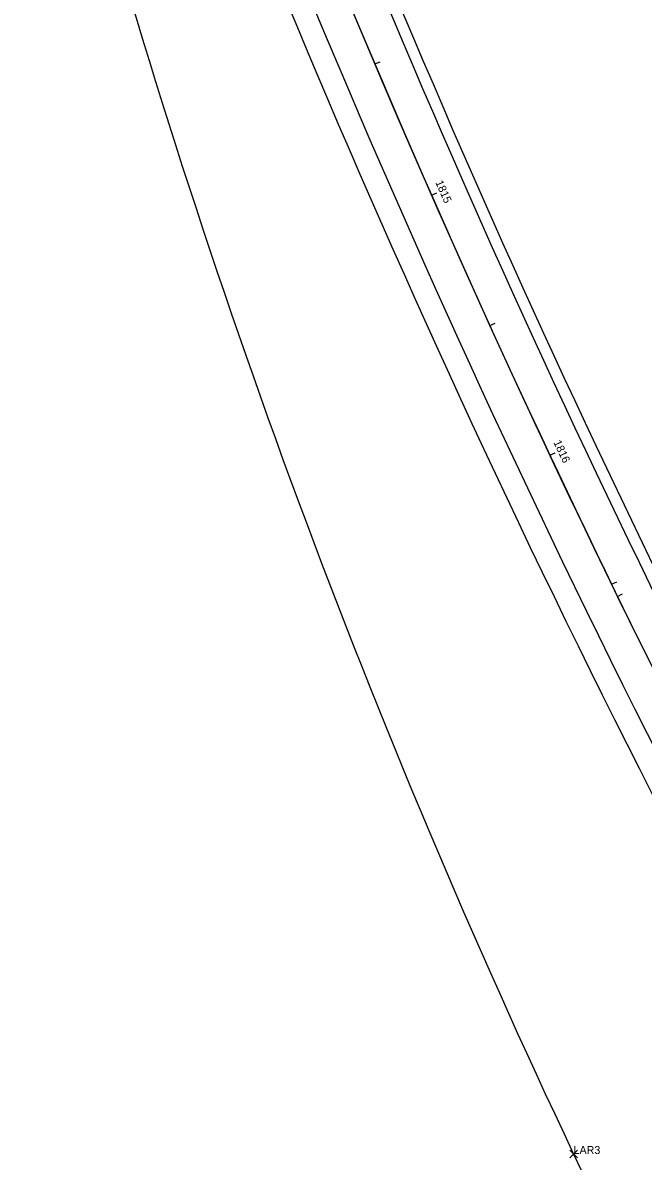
# Model space of a CAD drawing. Extents: x 6334 to 41599, y 9030 to 59113.
# Drawn here: x 20810.8 to 21027.9, y 34361.6 to 34759.9 of the extents above; entities that cross this region are included whole.
import ezdxf

# ---------------------------------------------------------------- set-up
doc = ezdxf.new("R2010")
doc.units = 0
for name, color, linetype in [('GE_X_CL_20', 7, 'Continuous'), ('GE_X_CL_50', 7, 'Continuous'), ('GK_Visualization', 7, 'Continuous'), ('PM_X_Lane_Line', 7, 'Continuous'), ('PV_X_EOP', 7, 'Continuous'), ('PV_X_Shoulder', 7, 'Continuous'), ('RW_X_Esmt_LA', 7, 'Continuous')]:
    doc.layers.add(name, color=color, linetype=linetype)

msp = doc.modelspace()

# ---------------------------------------------------------------- linework, layer by layer
at = {"layer": 'GE_X_CL_20'}
for p, q in [((20933.95, 34745.52), (20935.79, 34746.3)), ((20953.78, 34699.62), (20955.61, 34700.43)), ((20974.19, 34653.98), (20976.01, 34654.81)), ((20995.19, 34608.6), (20997, 34609.46)), ((21016.77, 34563.5), (21018.57, 34564.37)), ((21018.85, 34559.22), (21020.65, 34560.09))]:
    msp.add_line(p, q, dxfattribs=at)
msp.add_arc((24529.94, 36271.9), 3906.53, 186.21667, 209.21667, dxfattribs=at)
at = {"layer": 'GE_X_CL_50'}
msp.add_arc((32581.78, 39251.96), 12277.67, 194.525, 202.716667, dxfattribs=at)
at = {"layer": 'GK_Visualization'}
for p, q in [((21002.15, 34362.81), (21004.81, 34365.48)), ((21002.15, 34365.48), (21004.81, 34362.81))]:
    msp.add_line(p, q, dxfattribs=at)
for centre, radius, start, end in [((32581.78, 39251.96), 12277.67, 194.525, 202.716667), ((32581.78, 39251.96), 12277.67, 194.525, 202.716667), ((24529.91, 36271.94), 3906.53, 186.21497, 209.2138), ((24529.91, 36271.94), 3906.53, 186.21497, 209.2138), ((24529.94, 36271.9), 3906.53, 186.21667, 209.21667), ((24529.94, 36271.9), 3906.53, 186.21667, 209.21667)]:
    msp.add_arc(centre, radius, start, end, dxfattribs=at)
at = {"layer": 'PM_X_Lane_Line'}
for start in [186.21667, 191.33607]:
    msp.add_arc((24529.94, 36271.9), 3906.53, start, 209.21667, dxfattribs=at)
at = {"layer": 'PV_X_EOP'}
for centre, radius, start, end in [((24529.94, 36271.9), 3918.53, 191.33607, 209.21667), ((24531.79, 36272.61), 3896.49, 192.87045, 209.21252)]:
    msp.add_arc(centre, radius, start, end, dxfattribs=at)
at = {"layer": 'PV_X_Shoulder'}
for radius, start in [(3926.53, 191.34141), (3890.53, 192.86631)]:
    msp.add_arc((24529.94, 36271.9), radius, start, 209.21667, dxfattribs=at)
at = {"layer": 'RW_X_Esmt_LA'}
msp.add_line((21003.48, 34364.15), (21020.77, 34328.02), dxfattribs=at)
msp.add_arc((23569.82, 35580.33), 2839.93, 195.3477, 205.35619, dxfattribs=at)

# ---------------------------------------------------------------- texts
at = {"layer": 'GE_X_CL_20'}
for s, rotation, p in [('1815', 293.7329, (20955.07, 34704.13)), ('1816', 295.1996, (20996.37, 34613.15))]:
    msp.add_text(s, height=2.8, rotation=rotation, dxfattribs=at).set_placement(p)
at = {"layer": 'GK_Visualization'}
msp.add_text('LAR3', height=2.8, dxfattribs=at).set_placement((21003.48, 34364.15))

doc.saveas('drawing.dxf')
